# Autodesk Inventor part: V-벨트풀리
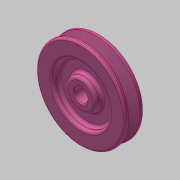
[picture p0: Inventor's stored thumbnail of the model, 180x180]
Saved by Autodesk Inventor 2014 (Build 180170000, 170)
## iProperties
Created: 2020-05
Part Number: V-벨트풀리
Material: 알루미늄 6061
Document SubType Name: Modeling
Designer: mduedu
Density: 1 g/cm^3
Appearance: 분홍색
Author: mduedu
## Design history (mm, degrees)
sketch "스케치1"
  geometry: L1 (-10, 0)-(10, 0); L2 (10, 47.5)-(-10, 47.5); L3 (-5.976, 47.5)-(-2.154, 35); L4 (-2.154, 35)-(2.154, 35); L5 (2.154, 35)-(5.976, 47.5); L6 (0, 0)-(0, 47.5); L7 (-10, 30)-(-3, 30); L8 (-3, 30)-(-3, 16); L9 (-3, 16)-(-10, 16); L10 (-10, 47.5)-(-10, 30); L11 (-10, 16)-(-10, 0); L12 (10, 30)-(3, 30); L13 (3, 30)-(3, 16); L14 (3, 16)-(10, 16); L15 (10, 0)-(10, 16); L16 (10, 30)-(10, 47.5); L17 (-4.6, 43)-(4.6, 43); 2 further points
  constraints: 34 end point, 6 parallel, 6 perpendicular, 4 point on line, 4 symmetric about line, 3 midpoint, 2 horizontal, 1 coincident, 1 collinear, 1 equal length, 1 vertical alignment
  dimensions: "d0" = 95 diameter of L2 L1; "d2" = 20 distance between parallel lines of L16 L10; "d3" = 6 distance between parallel lines of L13 L8; "d4" = 32 diameter of L14 L1; "d5" = 60 diameter of L12 L1; "d6" = 4.5 distance between parallel lines of L17 L2; "d7" = 8 distance between parallel lines of L4 L17; "d8" = 34 deg angle of L5 L3; "d9" = 9.2 distance of L17.start L17.end
revolve "회전1" sketch "스케치1" stored, may be unused: angle "d10" = 90 deg
sketch "스케치2"
  geometry: L1 (-2.5, 6.538)-(2.5, 6.538); L2 (2.5, 6.538)-(2.5, 9.3); L3 (2.5, 9.3)-(-2.5, 9.3); L4 (-2.5, 9.3)-(-2.5, 6.538); A1 r 7 centre (0, 0) between (-2.5, 6.538) and (2.5, 6.538); 1 further point
  constraints: 8 end point, 2 parallel, 2 point on circle, 1 centre point, 1 coincident, 1 horizontal, 1 perpendicular
  dimensions: "d11" = 14 diameter of A1; "d13" = 16.3 dimension on A1 L3; "d14" = 5 distance of L2.end L3.end
extrude "돌출1" cut sketch "스케치2" stored distance "d15" = 10; taper "d16" = 0 deg
chamfer "모따기1" distance "d17" = 1; stored, may be unused: second distance "d18" = 2, angle "d19" = 45 deg
fillet "모깎기1" dims "d20" = 3
fillet "모깎기2" dims "d21" = 2
fillet "모깎기3" dims "d22" = 1
fillet "모깎기4" dims "d23" = 0.5
fillet "모깎기5" dims "d24" = 3
node "솔리드1"
